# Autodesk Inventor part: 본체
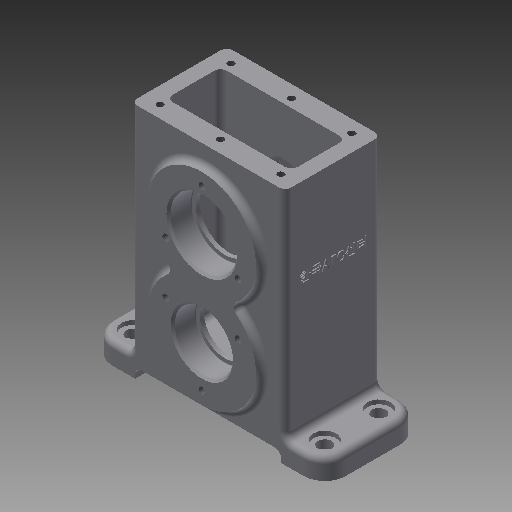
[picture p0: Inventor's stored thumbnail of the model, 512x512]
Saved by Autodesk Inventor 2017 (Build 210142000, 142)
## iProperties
Created: 2020-03
Part Number: 본체
Material: 일반
Document SubType Name: Modeling
Designer: mduedu
Density: 1 g/cm^3
Appearance: 기본값
Author: mduedu
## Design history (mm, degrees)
sketch "스케치1"
  geometry: L1 (-56, 0)-(56, 0); L2 (56, 0)-(56, 10); L3 (-56, 10)-(-56, 0); L4 (37, 10)-(37, 114); L5 (37, 114)-(-37, 114); L6 (-37, 114)-(-37, 10); L7 (56, 10)-(37, 10); L8 (-37, 10)-(-56, 10); L9 (0, 0)-(0, 114); 1 further point
  constraints: 18 end point, 5 parallel, 2 midpoint, 2 vertical, 1 coincident, 1 horizontal, 1 perpendicular
  dimensions: "d0" = 112 distance of L1.start L1.end; "d2" = 10 distance of L1.end L2.end; "d3" = 114 distance between parallel lines of L5 L1; "d4" = 74 distance between parallel lines of L4 L6
extrude "돌출1" new body sketch "스케치1" stored distance "d5" = 46; taper "d6" = 0 deg
sketch "스케치2"
  geometry: L1 (56, 0)-(-56, 0) reference; C1 r 26 at (0, 34); C2 r 26 at (0, 79); 1 further point
  constraints: 2 centre point, 2 vertical alignment, 1 equal radius
  dimensions: "d7" = 52 diameter of C2; "d9" = 34 distance from line of C1.centre L1; "d10" = 45 distance of C2.centre C1.centre
extrude "돌출2" join sketch "스케치2" stored distance "d11" = 52; taper "d12" = 0 deg
fillet "모깎기1" dims "d13" = 3
fillet "모깎기2" dims "d14" = 3
fillet "모깎기3" dims "d15" = 10
fillet "모깎기4" dims "d16" = 3
fillet "모깎기5" dims "d17" = 3
sketch "스케치3"
  geometry: L1 (-30, 114)-(30, 114); L2 (30, 114)-(30, 13); L3 (30, 13)-(-30, 13); L4 (-30, 13)-(-30, 114); L5 (-34, 114)-(34, 114) reference; L6 (46, 0)-(-46, 0) reference; 2 further points
  constraints: 8 end point, 2 parallel, 1 collinear, 1 horizontal, 1 midpoint, 1 perpendicular, 1 vertical alignment
  dimensions: "d18" = 60 distance between parallel lines of L2 L4; "d20" = 13 distance between parallel lines of L3 L6
extrude "돌출3" cut sketch "스케치3" stored distance "d21" = 26; taper "d22" = 0 deg
fillet "모깎기6" dims "d23" = 3
fillet "모깎기7" dims "d24" = 3
sketch "스케치4"
  geometry: L1 (-35, 0)-(35, 0); L2 (35, 0)-(35, 5); L3 (35, 5)-(-35, 5); L4 (-35, 5)-(-35, 0); 2 further points
  constraints: 8 end point, 2 parallel, 1 coincident, 1 horizontal, 1 midpoint, 1 perpendicular
  dimensions: "d25" = 70 distance of L1.start L1.end; "d27" = 5 distance of L1.end L2.end
extrude "돌출4" cut sketch "스케치4" stored distance "d28" = 26; taper "d29" = 0 deg
fillet "모깎기8" dims "d30" = 3
sketch "스케치5"
  geometry: A1 r 10 centre (-86, 33) between (-86, 43) and (-96, 33) reference; A2 r 10 centre (-86, 7) between (-96, 7) and (-86, -3) reference; A3 r 10 centre (6, 7) between (6, -3) and (16, 7) reference; A4 r 10 centre (6, 33) between (16, 33) and (6, 43) reference; 5 further points
  constraints: 4 coincident
hole "구멍1" sketch "스케치5" at (-86, 33), (-86, 7), (6, 7), (6, 33) diameter "d31" = 6.6; stored, may be unused: countersink angle "d35" = 90 deg, drill point angle "d37" = 118 deg; dims "d32" = 6, "d33" = 11, "d34" = 2, "d36" = 8
sketch "스케치6"
  geometry: A1 r 26 centre (0, 34) between (-16.403, 54.172) and (16.403, 54.172) reference; A2 r 3 centre (18.296, 56.5) between (16.403, 58.828) and (16.403, 54.172) reference; A3 r 26 centre (0, 79) between (16.403, 58.828) and (-16.403, 58.828) reference; A4 r 3 centre (-18.296, 56.5) between (-16.403, 54.172) and (-16.403, 58.828) reference; 2 further points
  constraints: 1 coincident
hole "구멍2" sketch "스케치6" at (0, 79) diameter "d38" = 28; stored, may be unused: countersink angle "d42" = 90 deg, drill point angle "d44" = 118 deg; dims "d39" = 6, "d40" = 32, "d41" = 11, "d43" = 8
sketch "스케치7"
  geometry: C1 r 16 at (0, 79) reference; A1 r 26 centre (0, 34) between (-16.403, 54.172) and (16.403, 54.172) reference; A2 r 3 centre (18.296, 56.5) between (16.403, 58.828) and (16.403, 54.172) reference; A3 r 26 centre (0, 79) between (16.403, 58.828) and (-16.403, 58.828) reference; A4 r 3 centre (-18.296, 56.5) between (-16.403, 54.172) and (-16.403, 58.828) reference; 2 further points
  constraints: 1 coincident
hole "구멍3" sketch "스케치7" at (0, 34) diameter "d45" = 24; stored, may be unused: countersink angle "d49" = 90 deg, drill point angle "d51" = 118 deg; dims "d46" = 6, "d47" = 28, "d48" = 11, "d50" = 8
sketch "스케치8"
  geometry: C1 r 14 at (0, 34) reference; A1 r 26 centre (0, 34) between (-16.403, 54.172) and (16.403, 54.172) reference; A2 r 3 centre (18.296, 56.5) between (16.403, 58.828) and (16.403, 54.172) reference; A3 r 26 centre (0, 79) between (16.403, 58.828) and (-16.403, 58.828) reference; A4 r 3 centre (-18.296, 56.5) between (-16.403, 54.172) and (-16.403, 58.828) reference; 2 further points
  constraints: 1 coincident
hole "구멍4" sketch "스케치8" at (0, 79) diameter "d52" = 24; stored, may be unused: countersink angle "d56" = 90 deg, drill point angle "d58" = 118 deg; dims "d53" = 6, "d54" = 28, "d55" = 11, "d57" = 8
sketch "스케치9" dims "d59" = 40
  geometry: C1 r 14 at (0, 34) reference; C2 r 16 at (0, 79) reference; A1 r 26 centre (0, 34) between (-16.403, 54.172) and (16.403, 54.172) reference; A2 r 3 centre (18.296, 56.5) between (16.403, 58.828) and (16.403, 54.172) reference; A3 r 26 centre (0, 79) between (16.403, 58.828) and (-16.403, 58.828) reference; A4 r 3 centre (-18.296, 56.5) between (-16.403, 54.172) and (-16.403, 58.828) reference; 3 further points
  constraints: 2 vertical alignment, 1 coincident, 2 other
hole "구멍5" sketch "스케치9" at (0, 99) diameter "d61" = 3.242; stored, may be unused: countersink angle "d65" = 90 deg, drill point angle "d67" = 118 deg; dims "d62" = 8, "d63" = 28, "d64" = 11, "d66" = 10
sketch "스케치10" dims "d71" = 40
  geometry: C1 r 1.621 at (17.321, 69) reference; C2 r 1.621 at (-17.321, 69) reference; C3 r 1.621 at (0, 99) reference; C4 r 14 at (0, 34) reference; C5 r 16 at (0, 79) reference; A1 r 26 centre (0, 34) between (-16.403, 54.172) and (16.403, 54.172) reference; A2 r 3 centre (18.296, 56.5) between (16.403, 58.828) and (16.403, 54.172) reference; A3 r 26 centre (0, 79) between (16.403, 58.828) and (-16.403, 58.828) reference; A4 r 3 centre (-18.296, 56.5) between (-16.403, 54.172) and (-16.403, 58.828) reference; 3 further points
  constraints: 2 vertical alignment, 1 coincident, 2 other
hole "구멍6" sketch "스케치10" at (0, 14) diameter "d72" = 3.242; stored, may be unused: countersink angle "d76" = 90 deg, drill point angle "d78" = 118 deg; dims "d73" = 8, "d74" = 28, "d75" = 11, "d77" = 10
sketch "스케치11"
  geometry: L1 (5, 6)-(63, 6); L2 (63, 6)-(63, 40); L3 (63, 40)-(5, 40); L4 (5, 40)-(5, 6); L5 (5, 6)-(63, 40); L6 (63, 6)-(5, 40); 7 further points
  constraints: 12 end point, 4 coincident, 4 midpoint, 2 parallel, 1 horizontal, 1 perpendicular
  dimensions: "d82" = 58 distance of L3.end L2.end; "d83" = 34 distance of L2.end L1.end
hole "구멍7" sketch "스케치11" at (5, 40), (63, 40), (63, 6), (5, 6), (34, 6), (34, 40) diameter "d84" = 3.242; stored, may be unused: countersink angle "d88" = 90 deg, drill point angle "d90" = 118 deg; dims "d85" = 8, "d86" = 28, "d87" = 11, "d89" = 10
fillet "모깎기9" dims "d91" = 0.3
chamfer "모따기1" distance "d92" = 1; stored, may be unused: second distance "d93" = 2, angle "d94" = 45 deg
sketch "스케치12"
  geometry: 2 further points
  constraints: 1 coincident
hole "구멍8" sketch "스케치12" at (0, -23) diameter "d95" = 4.917; stored, may be unused: countersink angle "d99" = 90 deg, drill point angle "d101" = 118 deg; dims "d96" = 8, "d97" = 12, "d98" = 1, "d100" = 10
sketch "스케치13"
  geometry: L1 (33, -13)-(7, -13) reference; L2 (40, 101)-(0, 101) reference; 3 further points
  constraints: 1 midpoint, 1 vertical alignment, 1 other
  dimensions: "d102" = 40 distance from line of point (20, 61) L2
feature "엠보싱1" sketch "스케치13" dims "d0" = 112, "d2" = 10, "d3" = 114, "d4" = 74, "d13" = 3, "d103" = 0.5, "d104" = 0
node "솔리드1"
mirror "대칭1"
pattern_circular "원형 패턴1" dims angle "d69" = 360 deg
pattern_circular "원형 패턴2" dims angle "d80" = 360 deg
mirror "대칭2"
node "투영된 루프1"
node "투영된 루프2"
node "투영된 루프3"
node "투영된 루프4"
node "투영된 루프5"
